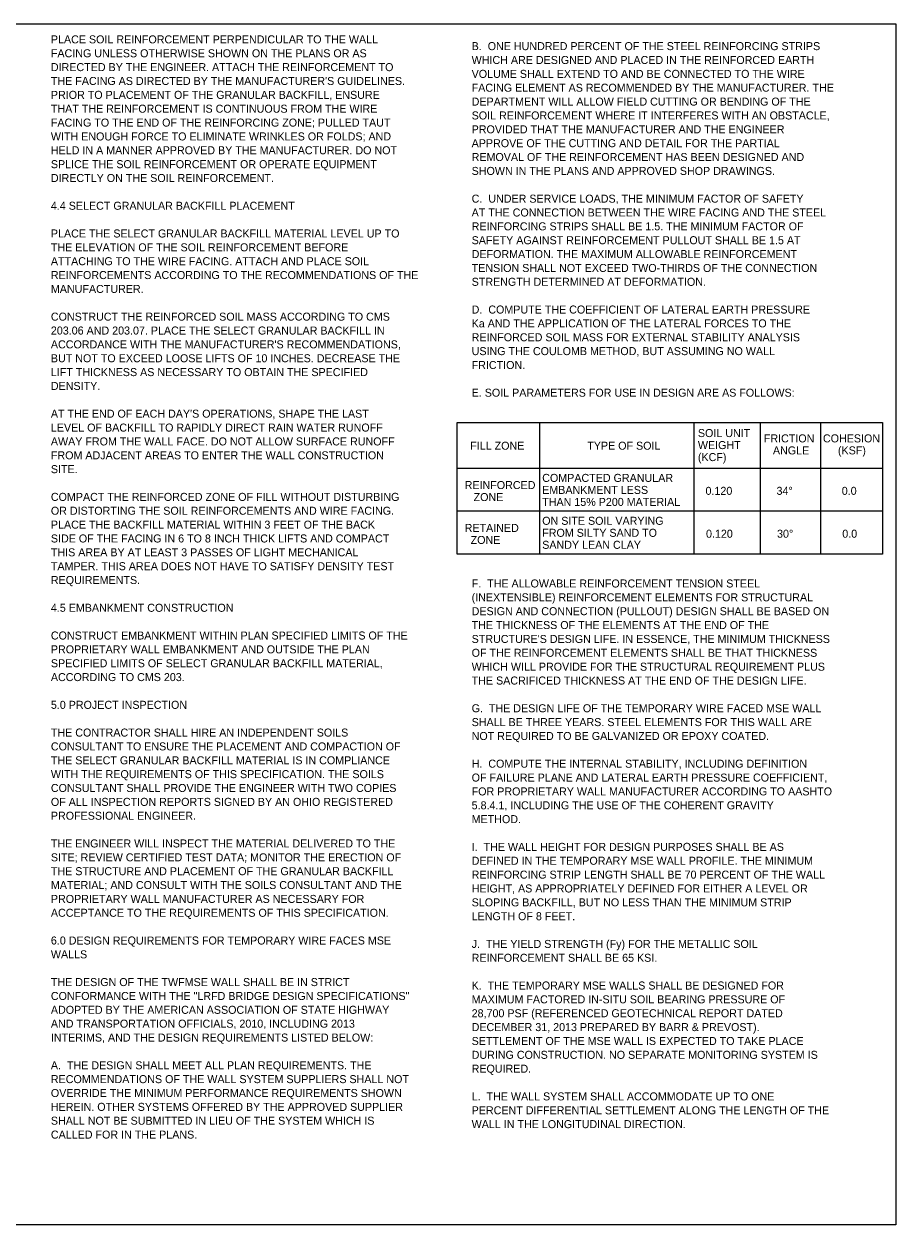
# Model space of a CAD drawing. Extents: x 1530552 to 1530730, y 675304 to 675366.
# Drawn here: x 1530670.04 to 1530685.29, y 675319.7 to 675340.7 of the extents above; entities that cross this region are included whole.
import ezdxf

# ---------------------------------------------------------------- set-up
doc = ezdxf.new("R2010")
doc.units = 0
doc.layers.add('BR_P_Gen_Text', color=7, linetype='Continuous')

msp = doc.modelspace()

# ---------------------------------------------------------------- linework, layer by layer
at = {"layer": 'BR_P_Gen_Text'}
for p, q in [((1530677.613, 675333.729), (1530685.05, 675333.729)), ((1530677.613, 675331.429), (1530677.613, 675333.729)), ((1530679.054, 675331.423), (1530679.054, 675333.722)), ((1530681.757, 675331.429), (1530681.757, 675333.729)), ((1530682.916, 675331.429), (1530682.916, 675333.729)), ((1530683.969, 675331.429), (1530683.969, 675333.729)), ((1530685.05, 675333.729), (1530685.05, 675331.429)), ((1530685.05, 675332.929), (1530677.613, 675332.929)), ((1530685.05, 675332.179), (1530677.613, 675332.179)), ((1530685.05, 675331.429), (1530677.613, 675331.429))]:
    msp.add_line(p, q, dxfattribs=at)
msp.add_lwpolyline([(1530654.785, 675340.699), (1530685.285, 675340.699), (1530685.285, 675319.699), (1530654.785, 675319.699)], close=True, dxfattribs=at)

# ---------------------------------------------------------------- texts
for s, p in [('PLACE SOIL REINFORCEMENT PERPENDICULAR TO THE WALL ', (1530670.505, 675340.36)), ('B.  ONE HUNDRED PERCENT OF THE STEEL REINFORCING STRIPS ', (1530677.864, 675340.242)), ('FACING UNLESS OTHERWISE SHOWN ON THE PLANS OR AS ', (1530670.505, 675340.117)), ('WHICH ARE DESIGNED AND PLACED IN THE REINFORCED EARTH ', (1530677.864, 675340)), ('DIRECTED BY THE ENGINEER. ATTACH THE REINFORCEMENT TO ', (1530670.505, 675339.875)), ('VOLUME SHALL EXTEND TO AND BE CONNECTED TO THE WIRE ', (1530677.864, 675339.757)), ("THE FACING AS DIRECTED BY THE MANUFACTURER'S GUIDELINES. ", (1530670.505, 675339.633)), ('FACING ELEMENT AS RECOMMENDED BY THE MANUFACTURER. THE ', (1530677.864, 675339.515)), ('PRIOR TO PLACEMENT OF THE GRANULAR BACKFILL, ENSURE ', (1530670.505, 675339.39)), ('THAT THE REINFORCEMENT IS CONTINUOUS FROM THE WIRE ', (1530670.505, 675339.148)), ('DEPARTMENT WILL ALLOW FIELD CUTTING OR BENDING OF THE ', (1530677.864, 675339.272)), ('FACING TO THE END OF THE REINFORCING ZONE; PULLED TAUT ', (1530670.505, 675338.905)), ('SOIL REINFORCEMENT WHERE IT INTERFERES WITH AN OBSTACLE, ', (1530677.864, 675339.03)), ('WITH ENOUGH FORCE TO ELIMINATE WRINKLES OR FOLDS; AND ', (1530670.505, 675338.663)), ('PROVIDED THAT THE MANUFACTURER AND THE ENGINEER ', (1530677.864, 675338.787)), ('APPROVE OF THE CUTTING AND DETAIL FOR THE PARTIAL ', (1530677.864, 675338.545)), ('HELD IN A MANNER APPROVED BY THE MANUFACTURER. DO NOT ', (1530670.505, 675338.421)), ('REMOVAL OF THE REINFORCEMENT HAS BEEN DESIGNED AND ', (1530677.864, 675338.303)), ('SPLICE THE SOIL REINFORCEMENT OR OPERATE EQUIPMENT ', (1530670.505, 675338.178)), ('SHOWN IN THE PLANS AND APPROVED SHOP DRAWINGS.', (1530677.864, 675338.06)), ('DIRECTLY ON THE SOIL REINFORCEMENT.', (1530670.505, 675337.936)), ('4.4 SELECT GRANULAR BACKFILL PLACEMENT', (1530670.505, 675337.451)), ('C.  UNDER SERVICE LOADS, THE MINIMUM FACTOR OF SAFETY ', (1530677.864, 675337.575)), ('AT THE CONNECTION BETWEEN THE WIRE FACING AND THE STEEL ', (1530677.864, 675337.333)), ('REINFORCING STRIPS SHALL BE 1.5. THE MINIMUM FACTOR OF ', (1530677.864, 675337.091)), ('PLACE THE SELECT GRANULAR BACKFILL MATERIAL LEVEL UP TO ', (1530670.505, 675336.966)), ('SAFETY AGAINST REINFORCEMENT PULLOUT SHALL BE 1.5 AT ', (1530677.864, 675336.848)), ('THE ELEVATION OF THE SOIL REINFORCEMENT BEFORE ', (1530670.505, 675336.724)), ('DEFORMATION. THE MAXIMUM ALLOWABLE REINFORCEMENT ', (1530677.864, 675336.606)), ('ATTACHING TO THE WIRE FACING. ATTACH AND PLACE SOIL ', (1530670.505, 675336.481)), ('TENSION SHALL NOT EXCEED TWO-THIRDS OF THE CONNECTION ', (1530677.864, 675336.363)), ('REINFORCEMENTS ACCORDING TO THE RECOMMENDATIONS OF THE ', (1530670.505, 675336.239)), ('MANUFACTURER.', (1530670.505, 675335.996)), ('STRENGTH DETERMINED AT DEFORMATION.', (1530677.864, 675336.121)), ('CONSTRUCT THE REINFORCED SOIL MASS ACCORDING TO CMS ', (1530670.505, 675335.512)), ('D.  COMPUTE THE COEFFICIENT OF LATERAL EARTH PRESSURE ', (1530677.864, 675335.636)), ('Ka AND THE APPLICATION OF THE LATERAL FORCES TO THE ', (1530677.864, 675335.394)), ('203.06 AND 203.07. PLACE THE SELECT GRANULAR BACKFILL IN ', (1530670.505, 675335.269)), ('REINFORCED SOIL MASS FOR EXTERNAL STABILITY ANALYSIS ', (1530677.864, 675335.151)), ("ACCORDANCE WITH THE MANUFACTURER'S RECOMMENDATIONS, ", (1530670.505, 675335.027)), ('USING THE COULOMB METHOD, BUT ASSUMING NO WALL ', (1530677.864, 675334.909)), ('BUT NOT TO EXCEED LOOSE LIFTS OF 10 INCHES. DECREASE THE ', (1530670.505, 675334.784)), ('FRICTION.', (1530677.864, 675334.666)), ('LIFT THICKNESS AS NECESSARY TO OBTAIN THE SPECIFIED ', (1530670.505, 675334.542)), ('DENSITY.', (1530670.505, 675334.3)), ('E. SOIL PARAMETERS FOR USE IN DESIGN ARE AS FOLLOWS:', (1530677.864, 675334.182)), ("AT THE END OF EACH DAY'S OPERATIONS, SHAPE THE LAST ", (1530670.505, 675333.815)), ('LEVEL OF BACKFILL TO RAPIDLY DIRECT RAIN WATER RUNOFF ', (1530670.505, 675333.572)), ('SOIL UNIT', (1530681.821, 675333.476)), ('AWAY FROM THE WALL FACE. DO NOT ALLOW SURFACE RUNOFF ', (1530670.505, 675333.33)), ('FILL ZONE', (1530677.839, 675333.255)), ('TYPE OF SOIL', (1530679.886, 675333.255)), ('WEIGHT', (1530681.821, 675333.266)), ('FRICTION', (1530682.974, 675333.383)), ('COHESION', (1530684.008, 675333.383)), ('FROM ADJACENT AREAS TO ENTER THE WALL CONSTRUCTION ', (1530670.505, 675333.087)), ('(KCF)', (1530681.821, 675333.056)), ('ANGLE', (1530683.133, 675333.173)), ('(KSF)', (1530684.27, 675333.173)), ('SITE.', (1530670.505, 675332.845)), ('REINFORCED', (1530677.742, 675332.567)), ('COMPACTED GRANULAR', (1530679.098, 675332.692)), ('COMPACT THE REINFORCED ZONE OF FILL WITHOUT DISTURBING ', (1530670.505, 675332.36)), ('   ZONE', (1530677.742, 675332.357)), ('EMBANKMENT LESS', (1530679.098, 675332.482)), ('0.120', (1530681.954, 675332.466)), ('34%%D', (1530683.196, 675332.466)), ('0.0', (1530684.337, 675332.466)), ('THAN 15% P200 MATERIAL', (1530679.098, 675332.272)), ('OR DISTORTING THE SOIL REINFORCEMENTS AND WIRE FACING. ', (1530670.505, 675332.118)), ('ON SITE SOIL VARYING', (1530679.098, 675331.942)), ('PLACE THE BACKFILL MATERIAL WITHIN 3 FEET OF THE BACK ', (1530670.505, 675331.875)), ('RETAINED', (1530677.742, 675331.817)), ('FROM SILTY SAND TO', (1530679.098, 675331.732)), ('SIDE OF THE FACING IN 6 TO 8 INCH THICK LIFTS AND COMPACT ', (1530670.505, 675331.633)), ('  ZONE', (1530677.742, 675331.607)), ('SANDY LEAN CLAY', (1530679.098, 675331.522)), ('0.120', (1530681.963, 675331.716)), ('30%%D', (1530683.205, 675331.716)), ('0.0', (1530684.346, 675331.716)), ('THIS AREA BY AT LEAST 3 PASSES OF LIGHT MECHANICAL ', (1530670.505, 675331.391)), ('TAMPER. THIS AREA DOES NOT HAVE TO SATISFY DENSITY TEST ', (1530670.505, 675331.148)), ('REQUIREMENTS.', (1530670.505, 675330.906)), ('F.  THE ALLOWABLE REINFORCEMENT TENSION STEEL ', (1530677.864, 675330.846)), ('(INEXTENSIBLE) REINFORCEMENT ELEMENTS FOR STRUCTURAL ', (1530677.864, 675330.604)), ('4.5 EMBANKMENT CONSTRUCTION', (1530670.505, 675330.421)), ('DESIGN AND CONNECTION (PULLOUT) DESIGN SHALL BE BASED ON ', (1530677.864, 675330.361)), ('THE THICKNESS OF THE ELEMENTS AT THE END OF THE ', (1530677.864, 675330.119)), ('CONSTRUCT EMBANKMENT WITHIN PLAN SPECIFIED LIMITS OF THE ', (1530670.505, 675329.936)), ("STRUCTURE'S DESIGN LIFE. IN ESSENCE, THE MINIMUM THICKNESS ", (1530677.864, 675329.876)), ('PROPRIETARY WALL EMBANKMENT AND OUTSIDE THE PLAN ', (1530670.505, 675329.694)), ('OF THE REINFORCEMENT ELEMENTS SHALL BE THAT THICKNESS ', (1530677.864, 675329.634)), ('SPECIFIED LIMITS OF SELECT GRANULAR BACKFILL MATERIAL, ', (1530670.505, 675329.451)), ('ACCORDING TO CMS 203.', (1530670.505, 675329.209)), ('WHICH WILL PROVIDE FOR THE STRUCTURAL REQUIREMENT PLUS ', (1530677.864, 675329.391)), ('THE SACRIFICED THICKNESS AT THE END OF THE DESIGN LIFE.', (1530677.864, 675329.149)), ('5.0 PROJECT INSPECTION', (1530670.505, 675328.724)), ('G.  THE DESIGN LIFE OF THE TEMPORARY WIRE FACED MSE WALL ', (1530677.864, 675328.664)), ('SHALL BE THREE YEARS. STEEL ELEMENTS FOR THIS WALL ARE ', (1530677.864, 675328.422)), ('THE CONTRACTOR SHALL HIRE AN INDEPENDENT SOILS ', (1530670.505, 675328.239)), ('NOT REQUIRED TO BE GALVANIZED OR EPOXY COATED.', (1530677.864, 675328.179)), ('CONSULTANT TO ENSURE THE PLACEMENT AND COMPACTION OF ', (1530670.505, 675327.997)), ('THE SELECT GRANULAR BACKFILL MATERIAL IS IN COMPLIANCE ', (1530670.505, 675327.754)), ('H.  COMPUTE THE INTERNAL STABILITY, INCLUDING DEFINITION ', (1530677.864, 675327.695)), ('WITH THE REQUIREMENTS OF THIS SPECIFICATION. THE SOILS ', (1530670.505, 675327.512)), ('OF FAILURE PLANE AND LATERAL EARTH PRESSURE COEFFICIENT, ', (1530677.864, 675327.452)), ('CONSULTANT SHALL PROVIDE THE ENGINEER WITH TWO COPIES ', (1530670.505, 675327.27)), ('FOR PROPRIETARY WALL MANUFACTURER ACCORDING TO AASHTO ', (1530677.864, 675327.21)), ('OF ALL INSPECTION REPORTS SIGNED BY AN OHIO REGISTERED ', (1530670.505, 675327.027)), ('5.8.4.1, INCLUDING THE USE OF THE COHERENT GRAVITY ', (1530677.864, 675326.967)), ('PROFESSIONAL ENGINEER.', (1530670.505, 675326.785)), ('METHOD.', (1530677.864, 675326.725)), ('THE ENGINEER WILL INSPECT THE MATERIAL DELIVERED TO THE ', (1530670.505, 675326.3)), ('SITE; REVIEW CERTIFIED TEST DATA; MONITOR THE ERECTION OF ', (1530670.505, 675326.057)), ('I.  THE WALL HEIGHT FOR DESIGN PURPOSES SHALL BE AS ', (1530677.864, 675326.24)), ('DEFINED IN THE TEMPORARY MSE WALL PROFILE. THE MINIMUM ', (1530677.864, 675325.998)), ('THE STRUCTURE AND PLACEMENT OF THE GRANULAR BACKFILL ', (1530670.505, 675325.815)), ('REINFORCING STRIP LENGTH SHALL BE 70 PERCENT OF THE WALL ', (1530677.864, 675325.755)), ('MATERIAL; AND CONSULT WITH THE SOILS CONSULTANT AND THE ', (1530670.505, 675325.573)), ('HEIGHT, AS APPROPRIATELY DEFINED FOR EITHER A LEVEL OR ', (1530677.864, 675325.513)), ('PROPRIETARY WALL MANUFACTURER AS NECESSARY FOR ', (1530670.505, 675325.33)), ('SLOPING BACKFILL, BUT NO LESS THAN THE MINIMUM STRIP ', (1530677.864, 675325.27)), ('ACCEPTANCE TO THE REQUIREMENTS OF THIS SPECIFICATION.', (1530670.505, 675325.088)), ('LENGTH OF 8 FEET.', (1530677.864, 675325.028)), ('6.0 DESIGN REQUIREMENTS FOR TEMPORARY WIRE FACES MSE ', (1530670.505, 675324.603)), ('J.  THE YIELD STRENGTH (Fy) FOR THE METALLIC SOIL ', (1530677.864, 675324.543)), ('WALLS', (1530670.505, 675324.361)), ('REINFORCEMENT SHALL BE 65 KSI.', (1530677.864, 675324.301)), ('THE DESIGN OF THE TWFMSE WALL SHALL BE IN STRICT ', (1530670.505, 675323.876)), ('K.  THE TEMPORARY MSE WALLS SHALL BE DESIGNED FOR ', (1530677.864, 675323.816)), ('CONFORMANCE WITH THE "LRFD BRIDGE DESIGN SPECIFICATIONS" ', (1530670.505, 675323.633)), ('MAXIMUM FACTORED IN-SITU SOIL BEARING PRESSURE OF ', (1530677.864, 675323.574)), ('ADOPTED BY THE AMERICAN ASSOCIATION OF STATE HIGHWAY ', (1530670.505, 675323.391)), ('28,700 PSF (REFERENCED GEOTECHNICAL REPORT DATED ', (1530677.864, 675323.331)), ('AND TRANSPORTATION OFFICIALS, 2010, INCLUDING 2013 ', (1530670.505, 675323.149)), ('INTERIMS, AND THE DESIGN REQUIREMENTS LISTED BELOW:', (1530670.505, 675322.906)), ('DECEMBER 31, 2013 PREPARED BY BARR & PREVOST). ', (1530677.864, 675323.089)), ('SETTLEMENT OF THE MSE WALL IS EXPECTED TO TAKE PLACE ', (1530677.864, 675322.846)), ('DURING CONSTRUCTION. NO SEPARATE MONITORING SYSTEM IS ', (1530677.864, 675322.604)), ('A.  THE DESIGN SHALL MEET ALL PLAN REQUIREMENTS. THE ', (1530670.505, 675322.421)), ('REQUIRED.', (1530677.864, 675322.362)), ('RECOMMENDATIONS OF THE WALL SYSTEM SUPPLIERS SHALL NOT ', (1530670.505, 675322.179)), ('OVERRIDE THE MINIMUM PERFORMANCE REQUIREMENTS SHOWN ', (1530670.505, 675321.936)), ('L.  THE WALL SYSTEM SHALL ACCOMMODATE UP TO ONE ', (1530677.864, 675321.877)), ('HEREIN. OTHER SYSTEMS OFFERED BY THE APPROVED SUPPLIER ', (1530670.505, 675321.694)), ('SHALL NOT BE SUBMITTED IN LIEU OF THE SYSTEM WHICH IS ', (1530670.505, 675321.452)), ('PERCENT DIFFERENTIAL SETTLEMENT ALONG THE LENGTH OF THE ', (1530677.864, 675321.634)), ('WALL IN THE LONGITUDINAL DIRECTION.', (1530677.864, 675321.392)), ('CALLED FOR IN THE PLANS.', (1530670.505, 675321.209))]:
    msp.add_text(s, height=0.14, dxfattribs=at).set_placement(p)

doc.saveas('drawing.dxf')
